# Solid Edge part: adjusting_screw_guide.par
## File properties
Title: Solid Edge 20
Author: vicky raina
Template: Normal.par
Last saved by: Robert a Rhodes jr
Revision: 2
Application: Solid Edge
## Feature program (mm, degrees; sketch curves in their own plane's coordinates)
sketch for "unnamed Protrusion 1" plane through (0, 0, 0) normal (0, -1, 0) x-axis (1, 0, 0)
  circle centre (0, 0) radius 7.9375
extrude "unnamed Protrusion 1" add finite 63.5 along +normal
sketch for "unnamed Protrusion 2" plane through (0, -63.5, 0) normal (0, -1, 0) x-axis (1, 0, 0)
  circle centre (0, 0) radius 6.3119
extrude "unnamed Protrusion 2" add finite 76.2 along +normal
chamfer "unnamed Chamfer 1"
sketch for "unnamed Cutout 1" plane through (0, 0, 0) normal (0, 0, 1) x-axis (1, 0, 0)
  line (1.1811, 0) -> (1.1811, -4.7498)
  line (1.1811, -4.7498) -> (-1.1811, -4.7498)
  line (-1.1811, -4.7498) -> (-1.1811, 0)
  line (-1.1811, 0) -> (1.1811, 0)
extrude "unnamed Cutout 1" cut finite 101.6 symmetric
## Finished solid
Body 1: solid body, 10 faces, 16 edges, 8 vertices.
  Faces by surface: plane 7, cylinder 2, cone 1
  Edges by curve: circle 8, line 8
Bounding box of the edges (mm): 15.875 x 139.700 x 15.875, from (-7.9375, -139.7, -7.9375) to (7.9375, 0, 7.9375).
Cylindrical faces by radius (mm): R6.3119 x1, R7.9375 x1
Conical faces (half-angle, radius in mm at the cone's reference point): 45 deg R6.3119 x1
Planar faces by outward normal: +x 1, +y 3, -x 1, -y 2
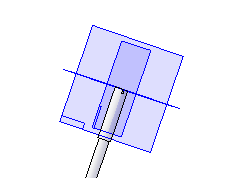
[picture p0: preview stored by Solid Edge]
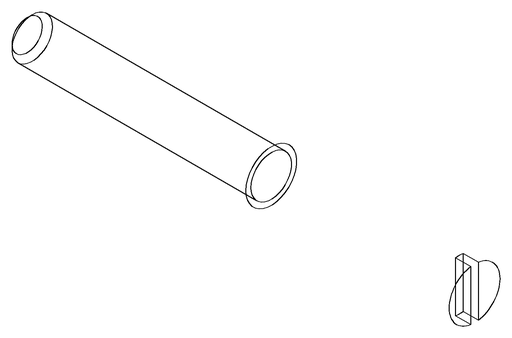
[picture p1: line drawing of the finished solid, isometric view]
